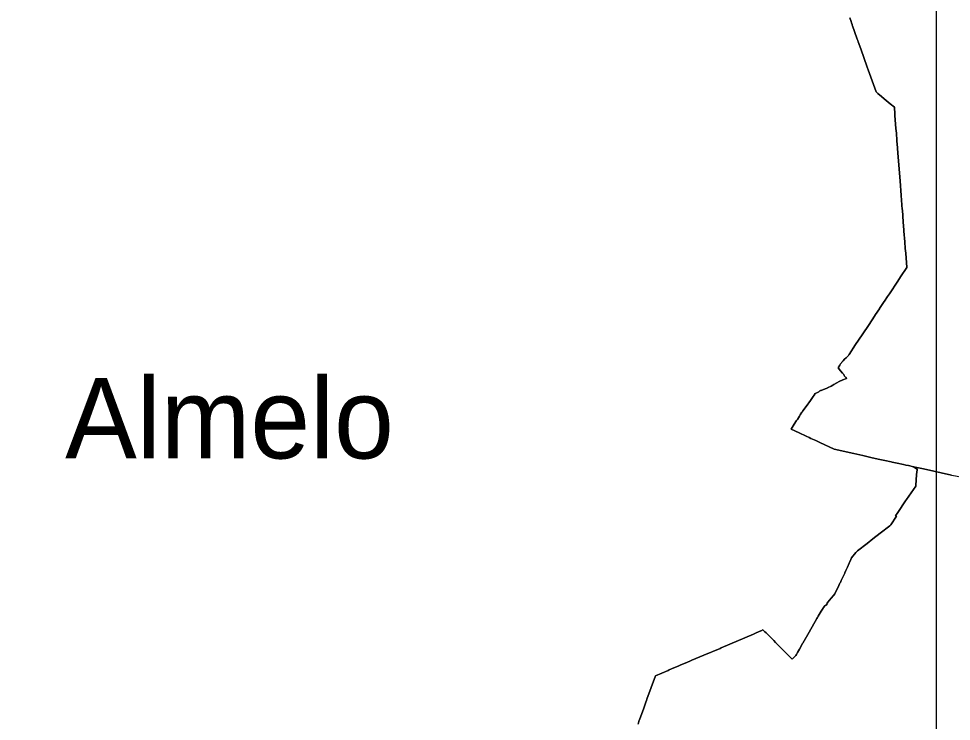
# Model space of a CAD drawing. Extents: x 113371 to 291721, y 393993 to 520143.
# Drawn here: x 240294 to 246091, y 482972 to 487336 of the extents above; entities that cross this region are included whole.
import ezdxf

# ---------------------------------------------------------------- set-up
doc = ezdxf.new("R2010")
doc.units = 0
for name, color, linetype in [('Boudingbox', 7, 'Continuous'), ('Default', 7, 'Continuous'), ('plaatsnamen', 7, 'Continuous'), ('vlieg gebied', 7, 'Continuous')]:
    doc.layers.add(name, color=color, linetype=linetype)

msp = doc.modelspace()

# ---------------------------------------------------------------- linework, layer by layer
at = {"layer": 'Boudingbox'}
msp.add_lwpolyline([(246000, 491500), (237000, 491500), (237000, 478500), (246000, 478500)], close=True, dxfattribs=at)
at = {"layer": 'Default'}
for points in [[(245772.745625, 486329.4525), (245761.175625, 486476.6525), (245757.025625, 486529.5925), (245756.355625, 486538.0425), (245755.145625, 486553.2325), (245753.115625, 486578.8325), (245749.595625, 486624.2525), (245747.245625, 486654.5725), (245740.985625, 486735.1825), (245739.165625, 486758.7625), (245738.215625, 486769.2325), (245737.045625, 486785.6425), (245711.135625, 486807.0725), (245674.245625, 486837.9825), (245657.085625, 486852.4325), (245635.265625, 486871.0025), (245623.285625, 486881.0825), (245574.505625, 487017.9125), (245568.395625, 487035.3825), (245527.785625, 487149.7825), (245512.405625, 487192.5625), (245509.175625, 487201.5425), (245506.735625, 487208.4725), (245490.085625, 487255.7625), (245476.955625, 487292.3025), (245475.575625, 487296.2725), (245474.515625, 487299.3125), (245470.875625, 487309.7525), (245470.795625, 487309.9825), (245467.785625, 487318.6125), (245459.665625, 487341.0725)], [(245459.665625, 487341.0725), (245467.785625, 487318.6125), (245470.795625, 487309.9825), (245470.875625, 487309.7525), (245474.515625, 487299.3125), (245475.575625, 487296.2725), (245476.955625, 487292.3025), (245490.085625, 487255.7625), (245506.735625, 487208.4725), (245509.175625, 487201.5425), (245512.405625, 487192.5625), (245527.785625, 487149.7825), (245568.395625, 487035.3825), (245574.505625, 487017.9125), (245623.285625, 486881.0825)], [(245623.285625, 486881.0825), (245635.265625, 486871.0025), (245657.085625, 486852.4325), (245674.245625, 486837.9825), (245711.135625, 486807.0725), (245737.045625, 486785.6425), (245738.215625, 486769.2325), (245739.165625, 486758.7625), (245740.985625, 486735.1825), (245747.245625, 486654.5725), (245749.595625, 486624.2525), (245753.115625, 486578.8325), (245755.145625, 486553.2325), (245756.355625, 486538.0425), (245757.025625, 486529.5925), (245761.175625, 486476.6525), (245772.745625, 486329.4525), (245779.875625, 486238.7225), (245786.675625, 486150.1925), (245786.805625, 486148.4625), (245792.655625, 486072.3125), (245796.305625, 486024.9225), (245796.905625, 486017.1025), (245802.065625, 485951.1425), (245805.315625, 485909.5525), (245807.565625, 485880.6325), (245807.575625, 485880.5625), (245814.635625, 485789.9425), (245776.145625, 485732.3925), (245758.475625, 485705.9825), (245706.005625, 485627.1425), (245695.295625, 485611.0625), (245676.235625, 485582.3925), (245674.695625, 485580.0625), (245645.595625, 485536.1925), (245644.015625, 485533.8025), (245620.415625, 485498.2225), (245613.795625, 485488.2425)], [(245398.075625, 485184.0425), (245402.655625, 485191.6325), (245407.995625, 485199.0725), (245411.465625, 485202.8425), (245419.795625, 485212.0225), (245428.195625, 485220.5125), (245436.705625, 485229.1525), (245448.345625, 485239.4625), (245450.185625, 485242.2225), (245451.285625, 485243.8825), (245451.545625, 485244.2625), (245454.575625, 485248.8225), (245455.285625, 485249.8825), (245496.605625, 485311.9925), (245536.695625, 485371.8025), (245579.885625, 485436.9225), (245613.795625, 485488.2425), (245620.415625, 485498.2225), (245644.015625, 485533.8025), (245645.595625, 485536.1925), (245674.695625, 485580.0625), (245676.235625, 485582.3925), (245695.295625, 485611.0625), (245706.005625, 485627.1425), (245758.475625, 485705.9825), (245776.145625, 485732.3925), (245814.635625, 485789.9425), (245807.575625, 485880.5625), (245807.565625, 485880.6325), (245805.315625, 485909.5525), (245802.065625, 485951.1425), (245796.905625, 486017.1025), (245796.305625, 486024.9225), (245792.655625, 486072.3125), (245786.805625, 486148.4625), (245786.675625, 486150.1925), (245779.875625, 486238.7225), (245772.745625, 486329.4525)], [(245613.795625, 485488.2425), (245579.885625, 485436.9225), (245536.695625, 485371.8025), (245496.605625, 485311.9925), (245455.285625, 485249.8825), (245454.575625, 485248.8225), (245451.545625, 485244.2625), (245451.285625, 485243.8825), (245450.185625, 485242.2225), (245448.345625, 485239.4625), (245436.705625, 485229.1525), (245428.195625, 485220.5125), (245419.795625, 485212.0225), (245411.465625, 485202.8425), (245407.995625, 485199.0725), (245402.655625, 485191.6325), (245398.075625, 485184.0425), (245388.205625, 485166.6025), (245401.885625, 485149.5825), (245414.995625, 485133.7025), (245418.515625, 485130.3825), (245422.095625, 485125.5925), (245424.475625, 485120.6625), (245426.735625, 485115.9625), (245428.615625, 485113.5525), (245433.555625, 485110.0225), (245437.765625, 485107.3825), (245439.535625, 485104.3425), (245440.295625, 485101.5125), (245415.855625, 485092.3625), (245394.835625, 485082.1625), (245380.375625, 485074.6025), (245361.805625, 485065.0625), (245354.305625, 485060.2625), (245343.765625, 485053.0225), (245326.325625, 485044.9825), (245322.495625, 485043.2025), (245318.545625, 485040.3725)], [(245168.965625, 484899.9525), (245189.215625, 484928.3825), (245215.015625, 484965.2125), (245233.185625, 484990.5425), (245238.335625, 484997.7225), (245245.845625, 485008.2525), (245255.795625, 485012.1025), (245259.495625, 485013.6925), (245263.105625, 485015.8525), (245267.765625, 485019.2825), (245271.115625, 485021.7125), (245274.525625, 485024.3125), (245278.615625, 485026.2025), (245282.335625, 485027.6825), (245297.485625, 485032.9725), (245313.875625, 485038.4725), (245318.545625, 485040.3725), (245322.495625, 485043.2025), (245326.325625, 485044.9825), (245343.765625, 485053.0225), (245354.305625, 485060.2625), (245361.805625, 485065.0625), (245380.375625, 485074.6025), (245394.835625, 485082.1625), (245415.855625, 485092.3625), (245440.295625, 485101.5125), (245439.535625, 485104.3425), (245437.765625, 485107.3825), (245433.555625, 485110.0225), (245428.615625, 485113.5525), (245426.735625, 485115.9625), (245424.475625, 485120.6625), (245422.095625, 485125.5925), (245418.515625, 485130.3825), (245414.995625, 485133.7025), (245401.885625, 485149.5825), (245388.205625, 485166.6025), (245398.075625, 485184.0425)], [(245318.545625, 485040.3725), (245313.875625, 485038.4725), (245297.485625, 485032.9725), (245282.335625, 485027.6825), (245278.615625, 485026.2025), (245274.525625, 485024.3125), (245271.115625, 485021.7125), (245267.765625, 485019.2825), (245263.105625, 485015.8525), (245259.495625, 485013.6925), (245255.795625, 485012.1025), (245245.845625, 485008.2525), (245238.335625, 484997.7225), (245233.185625, 484990.5425), (245215.015625, 484965.2125), (245189.215625, 484928.3825), (245168.965625, 484899.9525), (245165.325625, 484894.8425), (245164.085625, 484893.1025), (245163.585625, 484892.4025), (245162.845625, 484891.3625), (245152.445625, 484875.1825), (245152.185625, 484874.7725), (245147.715625, 484867.8125), (245147.645625, 484867.7025), (245134.165625, 484846.8925), (245129.645625, 484839.9225), (245115.295625, 484817.6625), (245102.075625, 484797.1125), (245095.445625, 484786.8925), (245145.795625, 484763.2725), (245188.195625, 484743.5725), (245207.245625, 484734.7125), (245218.755625, 484729.3525), (245248.005625, 484715.7225), (245248.375625, 484715.5525), (245257.065625, 484711.5025), (245273.875625, 484703.6725)], [(245877.525625, 484523.7125), (245878.015625, 484529.3225), (245878.885625, 484539.2825), (245856.665625, 484553.0025), (245824.345625, 484560.0225), (245807.585625, 484563.6625), (245793.245625, 484566.7725), (245754.295625, 484575.2325), (245724.185625, 484581.7725), (245716.805625, 484583.4025), (245677.895625, 484592.0425), (245636.465625, 484601.2325), (245590.355625, 484611.4725), (245540.445625, 484622.5425), (245485.965625, 484634.6325), (245363.595625, 484661.7825), (245273.875625, 484703.6725), (245257.065625, 484711.5025), (245248.375625, 484715.5525), (245248.005625, 484715.7225), (245218.755625, 484729.3525), (245207.245625, 484734.7125), (245188.195625, 484743.5725), (245145.795625, 484763.2725), (245095.445625, 484786.8925), (245102.075625, 484797.1125), (245115.295625, 484817.6625), (245129.645625, 484839.9225), (245134.165625, 484846.8925), (245147.645625, 484867.7025), (245147.715625, 484867.8125), (245152.185625, 484874.7725), (245152.445625, 484875.1825), (245162.845625, 484891.3625), (245163.585625, 484892.4025), (245164.085625, 484893.1025), (245165.325625, 484894.8425), (245168.965625, 484899.9525)], [(245273.875625, 484703.6725), (245363.595625, 484661.7825), (245485.965625, 484634.6325), (245540.445625, 484622.5425), (245590.355625, 484611.4725), (245636.465625, 484601.2325), (245677.895625, 484592.0425), (245716.805625, 484583.4025), (245724.185625, 484581.7725), (245754.295625, 484575.2325), (245793.245625, 484566.7725), (245807.585625, 484563.6625), (245824.345625, 484560.0225), (245856.665625, 484553.0025), (245917.765625, 484539.7325), (246091.575625, 484502.0025), (246116.895625, 484496.5025), (246126.735625, 484494.3625), (246182.755625, 484482.2025)], [(246091.575625, 484502.0025), (245917.765625, 484539.7325), (245856.665625, 484553.0025), (245878.885625, 484539.2825), (245878.015625, 484529.3225), (245877.525625, 484523.7125), (245873.315625, 484475.4425), (245870.105625, 484433.0725), (245812.545625, 484349.9125), (245806.305625, 484340.8925), (245757.855625, 484269.5225), (245743.545625, 484248.4325), (245750.685625, 484245.9025), (245715.985625, 484192.6525), (245708.155625, 484187.1325), (245648.755625, 484140.6925), (245603.015625, 484105.0425), (245567.365625, 484077.2625), (245507.765625, 484030.4725), (245496.665625, 484020.1125), (245496.755625, 484020.0825), (245471.225625, 483986.9225), (245466.025625, 483977.8625), (245457.785625, 483959.2525), (245456.125625, 483955.2525), (245445.455625, 483929.8925), (245436.285625, 483907.9225), (245430.225625, 483894.6525), (245429.025625, 483892.3225), (245416.565625, 483867.9525), (245405.905625, 483847.2325), (245402.225625, 483834.9025), (245399.175625, 483829.6225), (245396.895625, 483825.6525), (245392.555625, 483816.3625)], [(245320.245625, 483706.8425), (245323.275625, 483711.5325), (245334.115625, 483724.8625), (245345.285625, 483737.6825), (245358.065625, 483752.6825), (245366.715625, 483764.7525), (245371.965625, 483773.9325), (245379.215625, 483788.5025), (245392.555625, 483816.3625), (245396.895625, 483825.6525), (245399.175625, 483829.6225), (245402.225625, 483834.9025), (245405.905625, 483847.2325), (245416.565625, 483867.9525), (245429.025625, 483892.3225), (245430.225625, 483894.6525), (245436.285625, 483907.9225), (245445.455625, 483929.8925), (245456.125625, 483955.2525), (245457.785625, 483959.2525), (245466.025625, 483977.8625), (245471.225625, 483986.9225), (245496.755625, 484020.0825), (245496.665625, 484020.1125), (245507.765625, 484030.4725), (245567.365625, 484077.2625), (245603.015625, 484105.0425), (245648.755625, 484140.6925), (245708.155625, 484187.1325), (245715.985625, 484192.6525), (245750.685625, 484245.9025), (245743.545625, 484248.4325), (245757.855625, 484269.5225), (245806.305625, 484340.8925), (245812.545625, 484349.9125), (245870.105625, 484433.0725), (245873.315625, 484475.4425), (245877.525625, 484523.7125)], [(245392.555625, 483816.3625), (245379.215625, 483788.5025), (245371.965625, 483773.9325), (245366.715625, 483764.7525), (245358.065625, 483752.6825), (245345.285625, 483737.6825), (245334.115625, 483724.8625), (245323.275625, 483711.5325), (245320.245625, 483706.8425), (245318.105625, 483702.9025), (245317.155625, 483699.0725), (245316.955625, 483696.3225), (245311.555625, 483694.0825), (245304.665625, 483690.1525), (245296.165625, 483678.4525), (245294.025625, 483675.3925), (245282.005625, 483656.7425), (245263.335625, 483625.1125), (245259.145625, 483617.6625), (245255.835625, 483611.8025), (245206.895625, 483526.0725), (245167.345625, 483456.8325), (245166.295625, 483454.9825), (245146.465625, 483419.8825), (245135.435625, 483400.4525), (245128.015625, 483387.9025), (245125.225625, 483381.9925), (245101.485625, 483358.6425), (245081.485625, 483378.8125), (245058.475625, 483402.0025), (245036.485625, 483424.1725), (245010.595625, 483450.2625), (244998.785625, 483462.1625), (244987.325625, 483473.5525), (244966.725625, 483494.0225), (244939.585625, 483520.9825), (244932.895625, 483527.6425), (244920.515625, 483539.9725)], [(244661.165625, 483428.1025), (244860.995625, 483514.3525), (244873.795625, 483519.8625), (244877.175625, 483521.3125), (244907.455625, 483534.3425), (244907.855625, 483534.5225), (244913.595625, 483536.9925), (244914.435625, 483537.3525), (244920.515625, 483539.9725), (244932.895625, 483527.6425), (244939.585625, 483520.9825), (244966.725625, 483494.0225), (244987.325625, 483473.5525), (244998.785625, 483462.1625), (245010.595625, 483450.2625), (245036.485625, 483424.1725), (245058.475625, 483402.0025), (245081.485625, 483378.8125), (245101.485625, 483358.6425), (245125.225625, 483381.9925), (245128.015625, 483387.9025), (245135.435625, 483400.4525), (245146.465625, 483419.8825), (245166.295625, 483454.9825), (245167.345625, 483456.8325), (245206.895625, 483526.0725), (245255.835625, 483611.8025), (245259.145625, 483617.6625), (245263.335625, 483625.1125), (245282.005625, 483656.7425), (245294.025625, 483675.3925), (245296.165625, 483678.4525), (245304.665625, 483690.1525), (245311.555625, 483694.0825), (245316.955625, 483696.3225), (245317.155625, 483699.0725), (245318.105625, 483702.9025), (245320.245625, 483706.8425)], [(244920.515625, 483539.9725), (244914.435625, 483537.3525), (244913.595625, 483536.9925), (244907.855625, 483534.5225), (244907.455625, 483534.3425), (244877.175625, 483521.3125), (244873.795625, 483519.8625), (244860.995625, 483514.3525), (244661.165625, 483428.1025), (244655.085625, 483425.4825), (244552.365625, 483382.1825), (244478.585625, 483351.4325), (244469.595625, 483347.6825), (244447.435625, 483338.3225), (244419.525625, 483326.5425), (244404.775625, 483320.3125), (244393.645625, 483315.5725), (244366.175625, 483303.8925), (244336.455625, 483291.2525), (244330.765625, 483288.8225), (244251.585625, 483255.0125), (244199.255625, 483108.9125), (244196.535625, 483101.3925), (244192.495625, 483090.2125), (244177.195625, 483047.8425), (244173.635625, 483038.1825), (244152.915625, 482981.9825), (244152.475625, 482980.7225), (244151.775625, 482978.7225), (244143.665625, 482955.4725)], [(244143.665625, 482955.4725), (244151.775625, 482978.7225), (244152.475625, 482980.7225), (244152.915625, 482981.9825), (244173.635625, 483038.1825), (244177.195625, 483047.8425), (244192.495625, 483090.2125), (244196.535625, 483101.3925), (244199.255625, 483108.9125), (244251.585625, 483255.0125), (244330.765625, 483288.8225), (244336.455625, 483291.2525), (244366.175625, 483303.8925), (244393.645625, 483315.5725), (244404.775625, 483320.3125), (244419.525625, 483326.5425), (244447.435625, 483338.3225), (244469.595625, 483347.6825), (244478.585625, 483351.4325), (244552.365625, 483382.1825), (244655.085625, 483425.4825), (244661.165625, 483428.1025)]]:
    msp.add_lwpolyline(points, dxfattribs=at)
at = {"layer": 'vlieg gebied'}
msp.add_lwpolyline([(246000, 491500), (237000, 491500), (237000, 478500), (246000, 478500)], close=True, dxfattribs=at)

# ---------------------------------------------------------------- texts
at = {"layer": 'plaatsnamen'}
msp.add_text('Almelo', height=500, dxfattribs=at).set_placement((240582.246401, 484604.847563))

doc.saveas('drawing.dxf')
